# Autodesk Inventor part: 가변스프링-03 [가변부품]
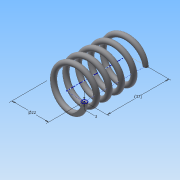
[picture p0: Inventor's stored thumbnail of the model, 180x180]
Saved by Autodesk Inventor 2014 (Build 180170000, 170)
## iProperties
Created: 2015-09
Part Number: 가변스프링-03 [가변부품]
Material: 강철, 탄소
Document SubType Name: Modeling
Designer: study
Density: 7.87 g/cm^3
Appearance: 반연마
Mass: 18.8111 g
Surface Area: 32.4633 cm^2
Volume: 2.39023 cm^3
Author: study
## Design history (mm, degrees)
sketch "스케치1"
  geometry: L1 (0, 0)-(11, 0); L2 (11, 0)-(11, 28.893); L3 (11, 28.893)-(0, 28.893); L4 (0, 28.893)-(0, 0); C1 r 1.5 at (11, 0)
  constraints: 8 end point, 2 parallel, 1 centre point, 1 coincident, 1 horizontal, 1 perpendicular
  dimensions: "d0" = 22 diameter of L2 L4; "d1" = 28.89259 distance of L1.end L2.end (derived); "d2" = 3 diameter of C1
feature "코일1" pitch "d3" = 10; turns "d5" = 5; dims "d4" = 28.89259 (= d1), "d6" = 0, angle "d7" = 90 deg, angle "d8" = 90 deg, "d9" = 0, "d10" = 0
node "작업 평면1"
sketch "스케치2"
  geometry: L1 (-12.5, 0)-(-9.5, 0) reference; 1 further point
  constraints: 1 horizontal alignment
extrude "돌출1" cut sketch "스케치2" stored distance "d12" = 10; taper "d13" = 0 deg
node "작업 평면2"
sketch "스케치3"
  geometry: L1 (-9.5, 0)-(-12.5, 0) reference; 1 further point
  constraints: 1 horizontal alignment
extrude "돌출2" cut sketch "스케치3" stored distance "d15" = 10; taper "d16" = 0 deg
node "솔리드1"
node "절단 모서리 투영1"
node "절단 모서리 투영2"
other parameters: "d11" = 0, "d14" = 28.89259 (= d1)
